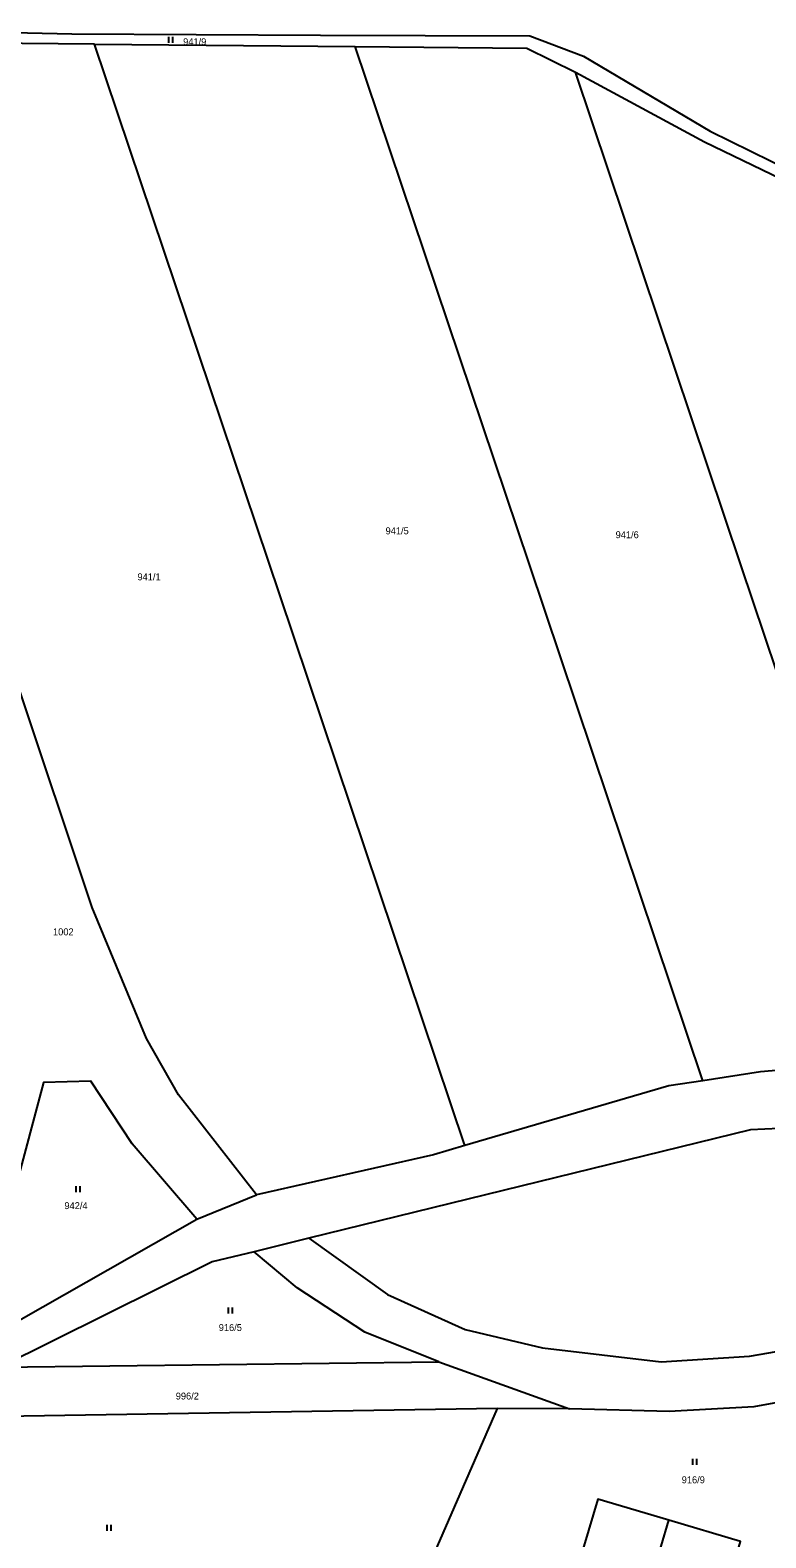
# Model space of a CAD drawing. Extents: x -7483133 to -743907, y -11317770 to -1129777.
# Drawn here: x -750439.3 to -750258.6, y -1131231.7 to -1130861.3 of the extents above; entities that cross this region are included whole.
import ezdxf

# ---------------------------------------------------------------- set-up
doc = ezdxf.new("R2010")
doc.units = 0
for name, color, linetype in [('Hranice parcel', 7, 'Continuous'), ('Parcelní čísla', 7, 'Continuous'), ('Značky kultur', 7, 'Continuous')]:
    doc.layers.add(name, color=color, linetype=linetype)

msp = doc.modelspace()

# ---------------------------------------------------------------- linework, layer by layer
at = {"layer": 'Hranice parcel'}
for p, q in [((-750423.45, -1130864.72), (-750359.42, -1130865.31)), ((-750398.36, -1131153.41), (-750383.69, -1131147.48)), ((-750370.85, -1131158.14), (-750384.23, -1131161.42)), ((-750446.64, -1131189.81), (-750338.88, -1131188.45)), ((-750338.88, -1131188.45), (-750306.79, -1131200.03)), ((-750324.56, -1131199.94), (-750360.45, -1131282.22)), ((-750306.79, -1131200.03), (-750324.56, -1131199.94)), ((-750292.72, -1131262.14), (-750282.4, -1131227.41))]:
    msp.add_line(p, q, dxfattribs=at)
for points in [[(-750491.25, -1130879.86), (-750469.04, -1130861.3), (-750429.04, -1130862.24), (-750367.95, -1130862.53), (-750316.54, -1130862.71), (-750303.39, -1130867.71), (-750272.3, -1130886.08), (-750242.29, -1130900.85), (-750215.89, -1130913.25), (-750197.91, -1130920.02), (-750183.56, -1130928.08)], [(-750423.45, -1130864.72), (-750467.96, -1130864.31), (-750489.98, -1130882.7)], [(-750332.51, -1131135.35), (-750377.98, -1131000.04), (-750423.45, -1130864.72)], [(-750359.42, -1130865.31), (-750317.3, -1130865.7), (-750305.36, -1130871.62)], [(-750274.04, -1131119.43), (-750316.73, -1130992.37), (-750359.42, -1130865.31)], [(-750305.36, -1130871.62), (-750273.65, -1130888.76), (-750217.17, -1130915.97), (-750205.4, -1130921.38)], [(-750223.88, -1131114.14), (-750264.62, -1130992.88), (-750305.36, -1130871.62)], [(-750383.69, -1131147.48), (-750402.83, -1131122.9), (-750410.73, -1131109.04), (-750424.07, -1131076.84), (-750442.36, -1131021.87), (-750466.73, -1130950.73), (-750487.24, -1130888.84), (-750489.98, -1130882.7)], [(-750223.88, -1131114.14), (-750259.94, -1131117.26), (-750274.04, -1131119.43)], [(-750398.36, -1131153.41), (-750414.23, -1131134.96), (-750424.36, -1131119.49), (-750435.97, -1131119.86), (-750442.91, -1131145.97), (-750457.63, -1131171.27), (-750469.94, -1131185.39), (-750472.83, -1131188.97)], [(-750370.85, -1131158.14), (-750351.54, -1131171.98), (-750332.45, -1131180.52), (-750313.48, -1131185.03), (-750284.31, -1131188.5), (-750262.6, -1131187.08), (-750237.96, -1131182.86), (-750198.96, -1131174.77), (-750007.37, -1131119.02)], [(-750007.37, -1131119.02), (-750096.89, -1131123.78), (-750262.33, -1131131.47), (-750370.85, -1131158.14)], [(-750274.04, -1131119.43), (-750282.4, -1131120.71), (-750332.51, -1131135.35)], [(-750332.51, -1131135.35), (-750340.2, -1131137.6), (-750383.69, -1131147.48)], [(-750472.83, -1131188.97), (-750452.8, -1131184.37), (-750398.36, -1131153.41)], [(-750384.23, -1131161.42), (-750394.55, -1131163.95), (-750446.64, -1131189.81)], [(-750338.88, -1131188.45), (-750357.11, -1131181.19), (-750373.67, -1131170.27), (-750384.23, -1131161.42)], [(-750213.06, -1131188.66), (-750241.04, -1131195.74), (-750261.52, -1131199.54), (-750282.31, -1131200.69), (-750306.79, -1131200.03)], [(-750324.56, -1131199.94), (-750440.85, -1131201.86), (-750460.37, -1131202.74), (-750475.17, -1131205.54), (-750485.93, -1131208.1)], [(-750282.4, -1131227.41), (-750299.84, -1131222.2), (-750310.14, -1131256.86)], [(-750275.17, -1131267.37), (-750264.83, -1131232.64), (-750282.4, -1131227.41)]]:
    msp.add_lwpolyline(points, dxfattribs=at)
at = {"layer": 'Značky kultur'}
for p, q in [((-750405.19, -1130864.45), (-750405.19, -1130862.95)), ((-750404.19, -1130864.45), (-750404.19, -1130862.95)), ((-750427.96, -1131146.79), (-750427.96, -1131145.29)), ((-750426.96, -1131146.79), (-750426.96, -1131145.29)), ((-750390.56, -1131176.61), (-750390.56, -1131175.11)), ((-750389.56, -1131176.61), (-750389.56, -1131175.11)), ((-750276.51, -1131213.81), (-750276.51, -1131212.31)), ((-750275.51, -1131213.81), (-750275.51, -1131212.31)), ((-750420.33, -1131230.02), (-750420.33, -1131228.52)), ((-750419.33, -1131230.02), (-750419.33, -1131228.52))]:
    msp.add_line(p, q, dxfattribs=at)

# ---------------------------------------------------------------- texts
at = {"layer": 'Parcelní čísla'}
for s, p in [('941/9', (-750401.69, -1130864.99)), ('941/5', (-750351.98, -1130985.16)), ('941/6', (-750295.49, -1130986.12)), ('941/1', (-750412.91, -1130996.47)), ('1002', (-750433.65, -1131083.69)), ('942/4', (-750430.85, -1131150.96)), ('916/5', (-750392.95, -1131180.91)), ('996/2', (-750403.51, -1131197.74)), ('916/9', (-750279.26, -1131218.32))]:
    msp.add_text(s, height=1.7, dxfattribs=at).set_placement(p)

doc.saveas('drawing.dxf')
